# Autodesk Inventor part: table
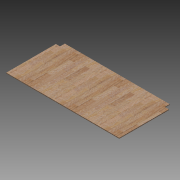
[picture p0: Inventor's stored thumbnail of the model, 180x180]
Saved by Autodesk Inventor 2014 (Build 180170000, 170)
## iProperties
Created: 2013-07
Part Number: table
Material: Generic
Document SubType Name: Modeling
Designer: Patrick Rice
Density: 1 g/cm^3
Appearance: Red Oak - Natural
Author: Patrick Rice
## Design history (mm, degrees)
sketch "Sketch1"
  geometry: L1 (-1172.966, 423.926)-(909.834, 423.926); L2 (909.834, 423.926)-(909.834, -490.474); L3 (909.834, -490.474)-(-1172.966, -490.474); L4 (-1172.966, -490.474)-(-1172.966, 423.926); L5 (833.634, 423.926)-(909.834, 423.926); L6 (909.834, 423.926)-(909.834, 423.926); L7 (-1096.766, -490.474)-(-1172.966, -490.474); L8 (-1172.966, -490.474)-(-1172.966, -401.574); L9 (909.834, -490.474)-(833.634, -490.474); L10 (909.834, -401.574)-(909.834, -490.474); L11 (-1172.966, 423.926)-(-1096.766, 423.926); L12 (-1172.966, 335.026)-(-1172.966, 423.926)
  constraints: 24 end point, 5 horizontal, 3 perpendicular, 2 parallel, 2 point on line, 1 other
  dimensions: "d19" = 914.4 distance of L3.end L1.start; "d20" = 2082.8 distance of L1.start L1.end
extrude "Extrusion2" new body sketch "Sketch1" distance "d21" = 14.6812; taper "d22" = 0 deg
body "Solid2"
